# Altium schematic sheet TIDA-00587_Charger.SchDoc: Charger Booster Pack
size 431 x 279 mm; VersionControl_RevNumber: E3; Date: Not shown in title block; ApprovedBy: Not shown in title block; CheckedBy: Gordon Varney; Author: Gordon Varney; CompanyName: Texas Instruments; DrawnBy: Gordon Varney; Engineer: Gordon Varney; Organization: Not shown in title block; Address1: Not shown in title block; Address2: Not shown in title block; Address3: Not shown in title block; Address4: Not shown in title block; DocumentNumber: 1; Revision: Use project parameter SCH_Rev; SheetNumber: 1; SheetTotal: 2; PageSetup: Record=PageOptions¦CenterHorizontal=True¦CenterVertical=True¦PrintScale=0.64¦XCorrection=1.00¦YCorrection=1.00¦PrintKind=0¦BorderSize=5000000¦LeftOffset=0¦BottomOffset=0¦Orientation=2¦PaperLength=1000¦PaperWidth=1000¦Scale=100¦PaperSource=15¦PrintQuality=600¦MediaType=1¦DitherType=10¦PrintScaleMode=1¦PaperKind=Letter
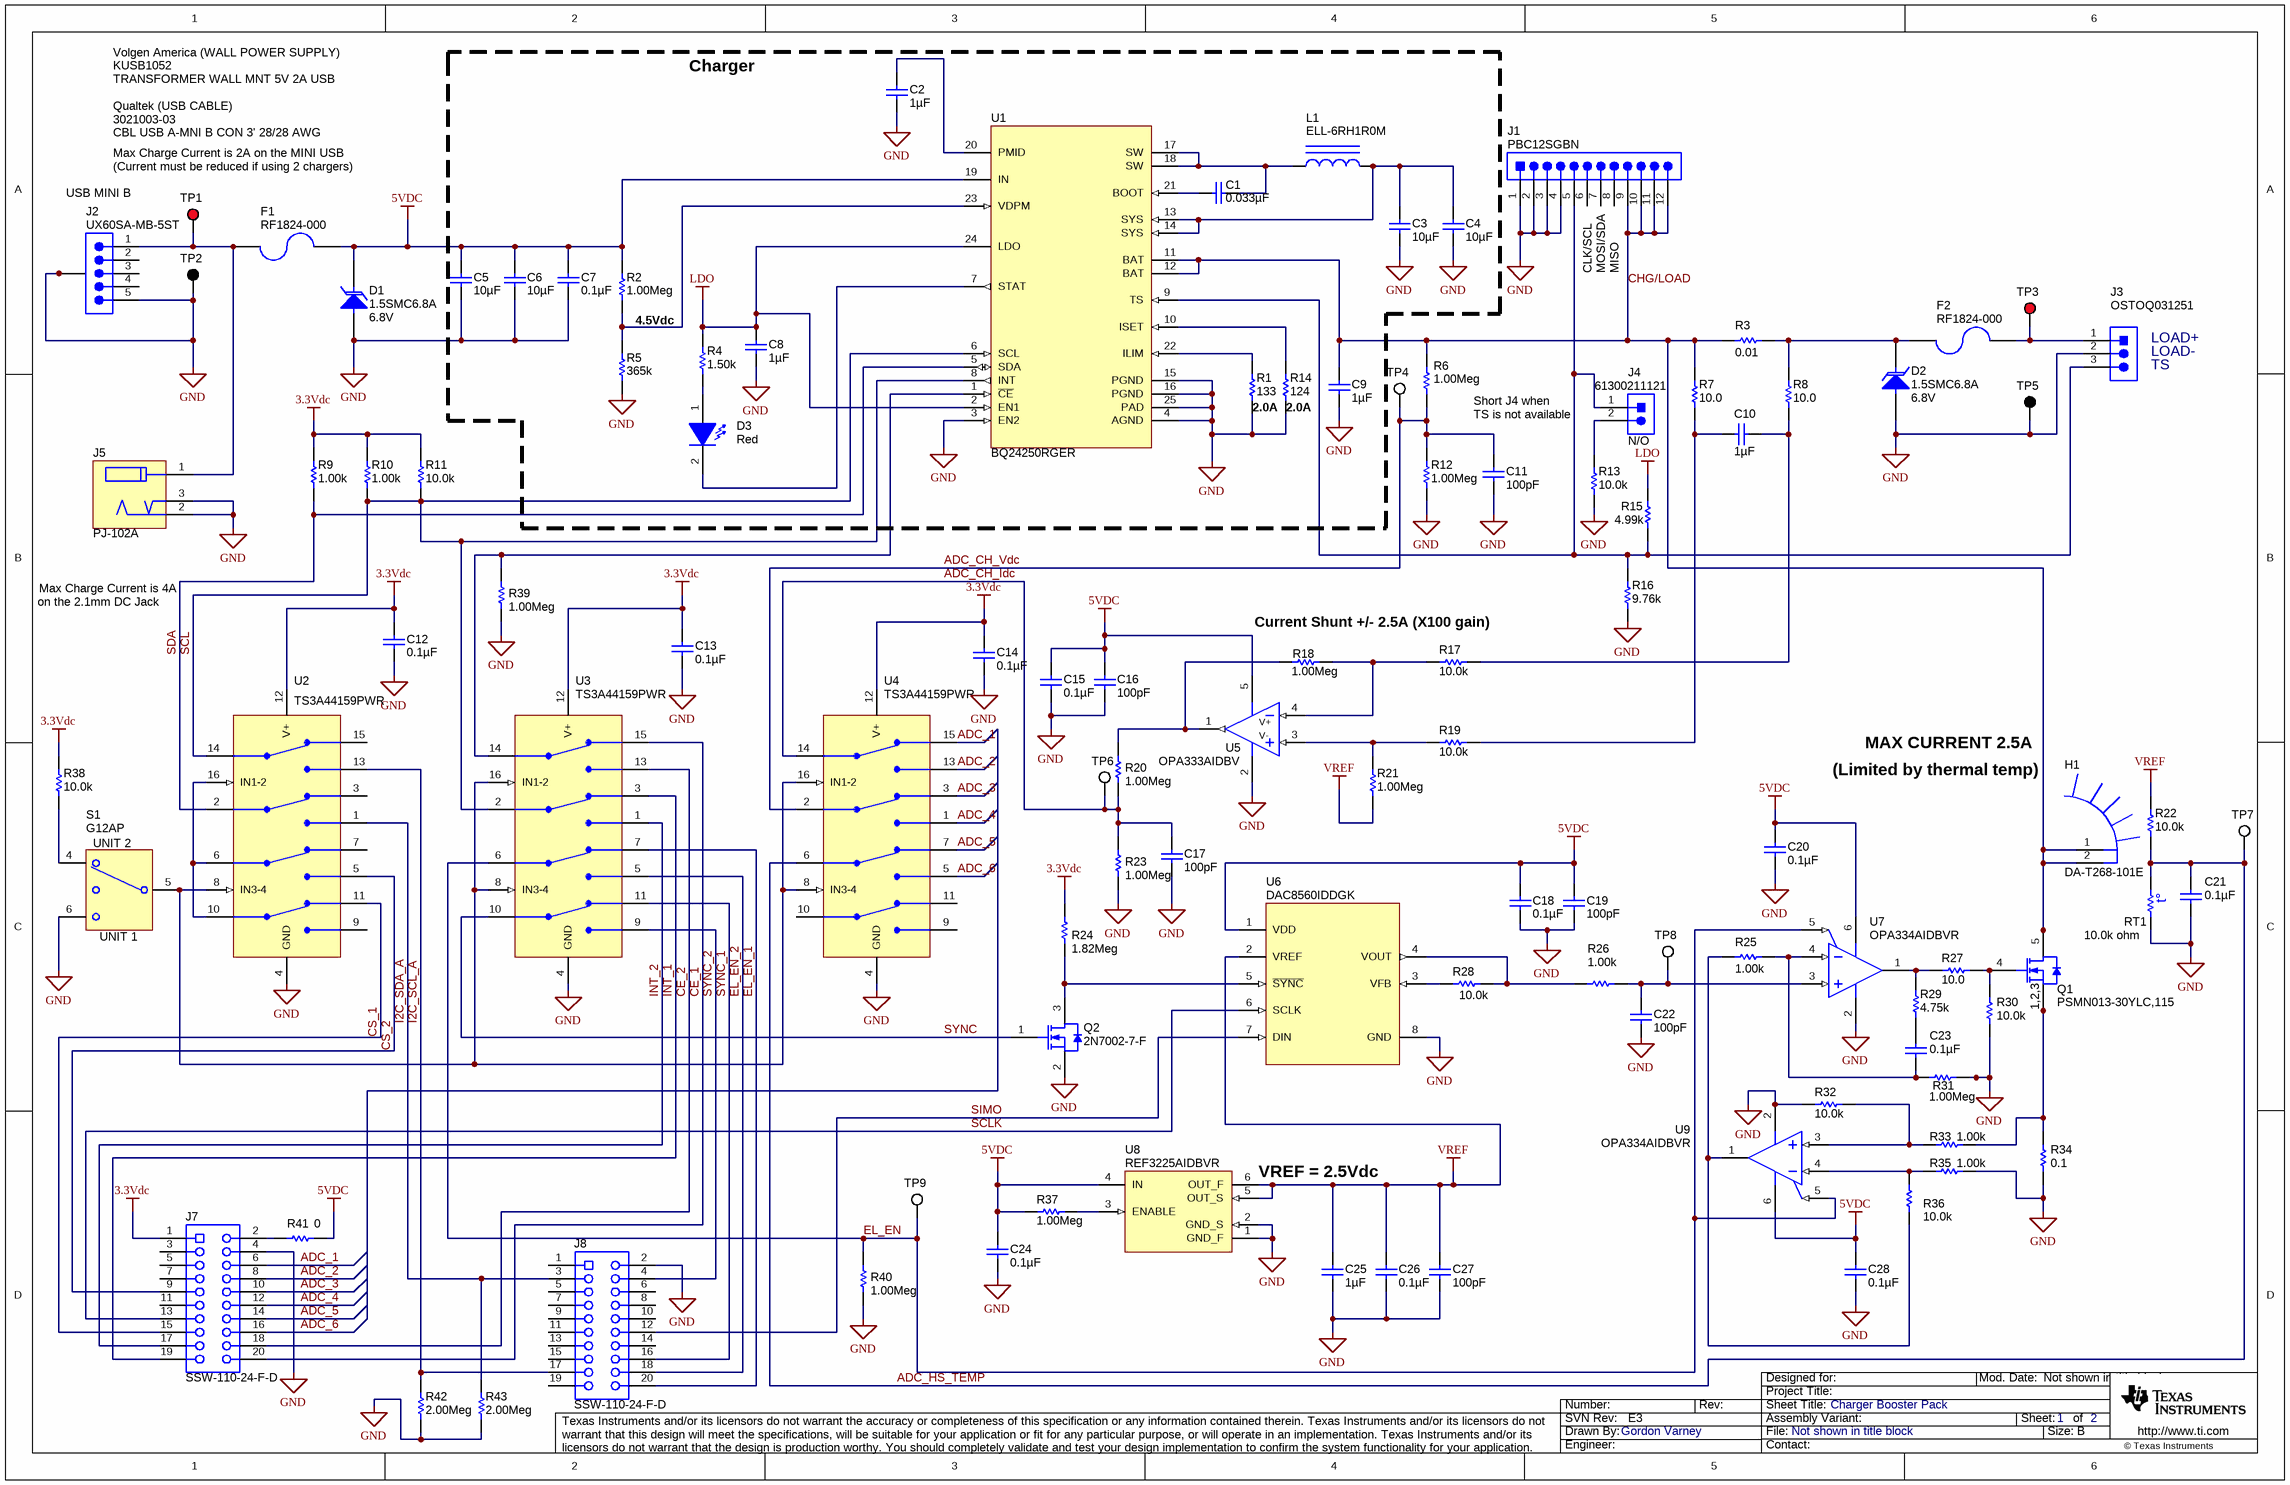
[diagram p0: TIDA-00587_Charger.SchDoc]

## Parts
C1  ValueDisplayed: 0.033µF  [0603]  (hidden comment: GRM188R71H333KA61D)
C2  ValueDisplayed: 1µF  [0805_HV]  (hidden comment: GRM21BR71E105KA99L)
C3  ValueDisplayed: 10µF  [0805_HV]  (hidden comment: GRM21BR61A106KE19L)
C4  ValueDisplayed: 10µF  [0805_HV]  (hidden comment: GRM21BR61A106KE19L)
C5  ValueDisplayed: 10µF  [0805_HV]  (hidden comment: GRM21BR61A106KE19L)
C6  ValueDisplayed: 10µF  [0805_HV]  (hidden comment: GRM21BR61A106KE19L)
C7  ValueDisplayed: 0.1µF  [0603]  (hidden comment: C0603C104K3RACTU)
C8  ValueDisplayed: 1µF  [0805_HV]  (hidden comment: GRM21BR71E105KA99L)
C9  ValueDisplayed: 1µF  [0805_HV]  (hidden comment: GRM21BR71E105KA99L)
C10  ValueDisplayed: 1µF  [0805_HV]  (hidden comment: GRM21BR71E105KA99L)
C11  ValueDisplayed: 100pF  [0603]  (hidden comment: C0603C101J5GACTU)
C12  ValueDisplayed: 0.1µF  [0603]  (hidden comment: C0603C104K3RACTU)
C13  ValueDisplayed: 0.1µF  [0603]  (hidden comment: C0603C104K3RACTU)
C14  ValueDisplayed: 0.1µF  [0603]  (hidden comment: C0603C104K3RACTU)
C15  ValueDisplayed: 0.1µF  [0603]  (hidden comment: C0603C104K3RACTU)
C16  ValueDisplayed: 100pF  [0603]  (hidden comment: GRM1885C1H101JA01D)
C17  ValueDisplayed: 100pF  [0603]  (hidden comment: C0603C101J5GACTU)
C18  ValueDisplayed: 0.1µF  [0603]  (hidden comment: C0603C104K3RACTU)
C19  ValueDisplayed: 100pF  [0603]  (hidden comment: GRM1885C1H101JA01D)
C20  ValueDisplayed: 0.1µF  [0603]  (hidden comment: C0603C104K3RACTU)
C21  ValueDisplayed: 0.1µF  [0603]  (hidden comment: GRM188R71E104KA01D)
C22  ValueDisplayed: 100pF  [0603]  (hidden comment: C0603C101J5GACTU)
C23  ValueDisplayed: 0.1µF  [0603]  (hidden comment: GRM188R71E104KA01D)
C24  ValueDisplayed: 0.1µF  [0603]  (hidden comment: C0603C104K3RACTU)
C25  ValueDisplayed: 1µF  [0805_HV]  (hidden comment: GRM21BR71E105KA99L)
C26  ValueDisplayed: 0.1µF  [0603]  (hidden comment: C0603C104K3RACTU)
C27  ValueDisplayed: 100pF  [0603]  (hidden comment: GRM1885C1H101JA01D)
C28  ValueDisplayed: 0.1µF  [0603]  (hidden comment: C0603C104K3RACTU)
D1  1.5SMC6.8A  value 6.8V  [SMC]
D2  1.5SMC6.8A  value 6.8V  [SMC]
D3  value Red  [LED_LTST-C190_Red]  (hidden comment: LTST-C190CKT)
F1  RF1824-000  [FUSE_LR2]
F2  RF1824-000  [FUSE_LR2]
H1  DA-T268-101E  [Ohmite_DA-T268-101E]
J1  PBC12SGBN  [Sullins_PBC12SGBN]
J2  UX60SA-MB-5ST  [UX60SA-MB-5ST]
J3  OSTOQ031251  [On-Shore_OSTOQ031251]
J4  61300211121  [WURTH_61300211121]
J5  PJ-102A  [CONN_PJ-102A]
J7  SSW-110-24-F-D  [CONN_SSW-110-23-F-D]
J8  SSW-110-24-F-D  [CONN_SSW-110-23-F-D]
L1  ELL-6RH1R0M  [ELL6RH]
Q1  PSMN013-30YLC,115  [LFPAK]
Q2  2N7002-7-F  [SOT-23]
R1  value 133  [0603]  (hidden comment: CRCW0603133RFKEA)
R2  value 1.00Meg  [0603]  (hidden comment: CRCW06031M00FKEA)
R3  value 0.01  [1206]  (hidden comment: LVK12R010DER)
R4  value 1.50k  [0603]  (hidden comment: CRCW06031K50FKEA)
R5  value 365k  [0603]  (hidden comment: CRCW0603365KFKEA)
R6  value 1.00Meg  [0603]  (hidden comment: CRCW06031M00FKEA)
R7  value 10.0  [0603]  (hidden comment: CRCW060310R0FKEA)
R8  value 10.0  [0603]  (hidden comment: CRCW060310R0FKEA)
R9  value 1.00k  [0603]  (hidden comment: CRCW06031K00FKEA)
R10  value 1.00k  [0603]  (hidden comment: CRCW06031K00FKEA)
R11  value 10.0k  [0603]  (hidden comment: CRCW060310K0FKEA)
R12  value 1.00Meg  [0603]  (hidden comment: CRCW06031M00FKEA)
R13  value 10.0k  [0603]  (hidden comment: CRCW060310K0FKEA)
R14  value 124  [0603]  (hidden comment: CRCW0603124RFKEA)
R15  value 4.99k  [0603]  (hidden comment: CRCW06034K99FKEA)
R16  value 9.76k  [0603]  (hidden comment: CRCW06039K76FKEA)
R17  value 10.0k  [0603]  (hidden comment: CRCW060310K0FKEA)
R18  value 1.00Meg  [0603]  (hidden comment: CRCW06031M00FKEA)
R19  value 10.0k  [0603]  (hidden comment: CRCW060310K0FKEA)
R20  value 1.00Meg  [0603]  (hidden comment: CRCW06031M00FKEA)
R21  value 1.00Meg  [0603]  (hidden comment: CRCW06031M00FKEA)
R22  value 10.0k  [0603]  (hidden comment: CRCW060310K0FKEA)
R23  value 1.00Meg  [0603]  (hidden comment: CRCW06031M00FKEA)
R24  value 1.82Meg  [0603]  (hidden comment: CRCW06031M82FKEA)
R25  value 1.00k  [0603]  (hidden comment: CRCW06031K00FKEA)
R26  value 1.00k  [0603]  (hidden comment: CRCW06031K00FKEA)
R27  value 10.0  [0603]  (hidden comment: CRCW060310R0FKEA)
R28  value 10.0k  [0603]  (hidden comment: CRCW060310K0FKEA)
R29  value 4.75k  [0603]  (hidden comment: CRCW06034K75FKEA)
R30  value 10.0k  [0603]  (hidden comment: CRCW060310K0FKEA)
R31  value 1.00Meg  [0603]  (hidden comment: CRCW06031M00FKEA)
R32  value 10.0k  [0603]  (hidden comment: CRCW060310K0FKEA)
R33  value 1.00k  [0603]  (hidden comment: CRCW06031K00FKEA)
R34  value 0.1  [2010M]  (hidden comment: CSRN2010FKR100)
R35  value 1.00k  [0603]  (hidden comment: CRCW06031K00FKEA)
R36  value 10.0k  [0603]  (hidden comment: CRCW060310K0FKEA)
R37  value 1.00Meg  [0603]  (hidden comment: CRCW06031M00FKEA)
R38  value 10.0k  [0603]  (hidden comment: CRCW060310K0FKEA)
R39  value 1.00Meg  [0603]  (hidden comment: CRCW06031M00FKEA)
R40  value 1.00Meg  [0603]  (hidden comment: CRCW06031M00FKEA)
R41  ValueDisplayed: 0  [0603]  (hidden comment: CRCW06030000Z0EA)
R42  value 2.00Meg  [0603]  (hidden comment: CRCW06032M00FKEA)
R43  value 2.00Meg  [0603]  (hidden comment: CRCW06032M00FKEA)
RT1  value 10.0k ohm  [0603]  (hidden comment: ERT-J1VG103FA)
S1  G12AP  [SW_G1xAP]
TP1  5000  [Keystone5000]  (value not drawn)
TP2  5001  [Keystone5001]  (value not drawn)
TP3  5000  [Keystone5000]  (value not drawn)
TP4  5002  [Keystone5002]  (value not drawn)
TP5  5001  [Keystone5001]  (value not drawn)
TP6  5002  [Keystone5002]  (value not drawn)
TP7  5002  [Keystone5002]  (value not drawn)
TP8  5002  [Keystone5002]  (value not drawn)
TP9  5002  [Keystone5002]  (value not drawn)
U1  BQ24250RGER  [RGE0024H_NV]
U2  TS3A44159PWR  [PW0016A_N]
U3  TS3A44159PWR  [PW0016A_N]
U4  TS3A44159PWR  [PW0016A_N]
U5  OPA333AIDBV  [DBV0005A_N]
U6  DAC8560IDDGK  [DGK0008A_N]
U7  OPA334AIDBVR  [DBV0006A_N]
U8  REF3225AIDBVR  [DBV0006A_N]
U9  OPA334AIDBVR  [DBV0006A_N]

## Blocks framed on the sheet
Charger: C1-C9 D3 L1 R1 R2 R4 R5 R14 U1

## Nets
3.3Vdc: C12.1 C13.1 C14.1 J7.1 R9.2 R10.2 R11.2 R24.1 R38.2 U2.12(V+) U3.12(V+) U4.12(V+)
5VDC: C5.1 C6.1 C7.1 C15.1 C16.1 C18.1 C19.1 C20.1 C24.1 C28.1 D1.1(K) F1.2 R2.2 R37.2 R41.1 U1.19(IN) U5.5(V+) U6.1(VDD) U7.6(V+) U8.4(IN) U9.6(V+)
GND: C2.1 C3.2 C4.2 C5.2 C6.2 C7.2 C8.1 C9.1 C11.2 C12.2 C13.2 C14.2 C15.2 C16.2 C17.2 C18.2 C19.2 C20.2 C21.2 C22.2 C24.2 C25.1 C26.2 C27.2 C28.2 D1.2(A) D2.2(A) J1.1 J1.2 J1.3 J1.4 J2.5 J2.6(GND) J2.7(GND) J2.8(GND) J2.9(GND) J3.2 J5.2 J5.3 J7.4 J8.2 Q2.2(S) R1.1 R5.1 R12.1 R13.1 R14.1 R16.1 R23.1 R30.1 R31.2 R32.2 R34.1 R35.2 R39.1 R40.1 R42.1 R43.1 RT1.1 S1.6 TP2.1 TP5.1 U1.3(EN2) U1.4(AGND) U1.15(PGND) U1.16(PGND) U1.25(PAD) U2.4(GND) U3.4(GND) U4.4(GND) U5.2(V-) U6.8(GND) U7.2(V-) U8.1(GND_F) U8.2(GND_S) U9.2(V-)
LDO: C8.2 R4.1 R15.2 U1.2(EN1) U1.24(LDO)
VREF: C25.2 C26.1 C27.1 R21.2 R22.2 U6.2(VREF) U8.5(OUT_S) U8.6(OUT_F)
ADC_1: J7.6 U4.15(NC1)
ADC_2: J7.8 U4.13(NO1)
ADC_3: J7.10 U4.3(NC2)
ADC_4: J7.12 U4.1(NO2)
ADC_5: J7.14 U4.7(NC3)
ADC_6: J7.16 U4.5(NO3)
ADC_CH_Idc: C17.1 R20.1 R23.2 TP6.1 U4.14(COM1)
ADC_CH_Vdc: C11.1 R6.1 R12.2 TP4.1 U4.2(COM2)
ADC_HS_TEMP: C21.1 R22.1 RT1.2 TP7.1 U4.6(COM3)
CE_1: J7.20 U3.15(NC1)
CE_2: J7.18 U3.13(NO1)
CHG/LOAD: C9.2 H1.1 H1.2 J1.9 J1.10 J1.11 J1.12 Q1.5(D) Q1.6(D) R3.1 R6.2 R7.2 U1.11(BAT) U1.12(BAT)
CS_1: J7.15 U2.11(NC4)
CS_2: J7.9 U2.5(NO3)
EL_EN: R40.2 TP9.1 U3.6(COM3) U7.5(ENABLE) U9.5(ENABLE)
EL_EN_1: J8.20 U3.7(NC3)
EL_EN_2: J8.18 U3.5(NO3)
I2C_SCL_A: J8.17 R42.2 U2.13(NO1)
I2C_SDA_A: J8.3 R43.2 U2.1(NO2)
INT_1: J7.19 U3.3(NC2)
INT_2: J7.17 U3.1(NO2)
SCL: R10.1 R11.1 U1.6(SCL) U1.8(INT) U2.14(COM1) U3.2(COM2)
SCLK: J7.13 U6.6(SCLK)
SDA: R9.1 U1.5(SDA) U2.2(COM2)
SIMO: J8.12 U6.7(DIN)
SYNC: Q2.1(G) U3.10(COM4)
SYNC_1: J8.16 U3.11(NC4)
SYNC_2: J8.4 U3.9(NO4)
NetC1_1: C1.1 L1.1 U1.17(SW) U1.18(SW)
NetC1_2: C1.2 U1.21(BOOT)
NetC2_2: C2.2 U1.20(PMID)
NetC3_1: C3.1 C4.1 L1.2 U1.13(SYS) U1.14(SYS)
NetC10_1: C10.1 R8.1 R17.2
NetC10_2: C10.2 R7.1 R19.2
NetC22_1: C22.1 R26.2 TP8.1 U7.3(IN+)
NetC23_1: C23.1 R29.1
NetC23_2: C23.2 R25.2 R31.1 U7.4(IN-)
NetD2_1: D2.1(K) F2.1 R3.2 R8.2
NetD3_1: D3.1(A) R4.2
NetD3_2: D3.2(K) U1.7(STAT)
NetF1_1: F1.1 J2.1 J5.1 TP1.1
NetF2_2: F2.2 J3.1 TP3.1
NetJ1_5: J1.5 J3.3 J4.1 R15.1 R16.2 U1.9(TS)
NetJ4_2: J4.2 R13.2
NetJ7_2: J7.2 R41.2
NetQ1_1: Q1.1(S) Q1.2(S) Q1.3(S) R33.2 R34.2
NetQ1_4: Q1.4(G) R27.2 R30.2
NetQ2_3: Q2.3(D) R24.2 U6.5(~{SYNC})
NetR1_2: R1.2 U1.22(ILIM)
NetR2_1: R2.1 R5.2 U1.23(VDPM)
NetR14_2: R14.2 U1.10(ISET)
NetR17_1: R17.1 R18.1 U5.4(IN-)
NetR18_2: R18.2 R20.2 U5.1(OUT)
NetR19_1: R19.1 R21.1 U5.3(IN+)
NetR25_1: R25.1 R36.1 U9.1(OUT)
NetR26_1: R26.1 R28.2 U6.4(VOUT)
NetR27_1: R27.1 R29.2 U7.1(OUT)
NetR28_1: R28.1 U6.3(VFB)
NetR32_1: R32.1 R33.1 U9.3(IN+)
NetR35_1: R35.1 R36.2 U9.4(IN-)
NetR37_1: R37.1 U8.3(ENABLE)
NetR38_1: R38.1 S1.4
NetR39_2: R39.2 U1.1(~{CE}) U3.14(COM1)
NetS1_5: S1.5(COM) U2.8(IN3-4) U3.8(IN3-4) U3.16(IN1-2) U4.8(IN3-4) U4.16(IN1-2)
NetU2_6: U2.6(COM3) U2.10(COM4) U2.16(IN1-2)

Not connected (* = marked no-connect by the designer): J1 6 7 8; J2 2 3 4; J7 3 5 7 11; J8 1 5 6 7 8 9 10 11 13 14 15 19; U2 3(NC2) 7(NC3) 9(NO4) 15(NC1); U4 9(NO4) 10(COM4) 11(NC4)

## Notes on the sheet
- Volgen America (WALL POWER SUPPLY)
- KUSB1052
- TRANSFORMER WALL MNT 5V 2A USB
- Qualtek (USB CABLE)
- 3021003-03
- CBL USB A-MNI B CON 3' 28/28 AWG
- Max Charge Current is 2A on the MINI USB
- (Current must be reduced if using 2 chargers)
- USB MINI B
- (near J1) CLK/SCL
- (near J1) MOSI/SDA
- MISO
- 4.5Vdc
- (near J3) LOAD+
- (near J3) LOAD-
- (near R1) 2.0A
- (near R14) 2.0A
- Short J4 when
- TS is not available
- (near J4) N/O
- (near J3) TS
- Max Charge Current is 4A
- on the 2.1mm DC Jack
- Current Shunt +/- 2.5A (X100 gain)
- (Limited by thermal temp)
- MAX CURRENT 2.5A
- (near S1) UNIT 2
- (near S1) UNIT 1
- (near U8) VREF = 2.5Vdc

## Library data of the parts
C1 = GRM188R71H333KA61D: CAP, CERM, 0.033uF, 50V, +/-10%, X7R, 0603; Manufacturer: MuRata; Polarized: N; CompType: Capacitor; U/M: EA; Cap_F: 0.000000033; Tolerance_%: 10; Value1: Unknown; VDC_V: 50; TaMin_C: -55; TaMax_C: 125
C2 C8-C10 C25 = GRM21BR71E105KA99L: CAP, CERM, 1uF, 25V, +/-10%, X7R, 0805; Manufacturer: MuRata; Polarized: N; CompType: Capacitor; U/M: EA; Cap_F: 0.000001; Tolerance_%: 10; Value1: Unknown; VDC_V: 25; TaMin_C: -55; TaMax_C: 125; Cap_Case: 0805
C3-C6 = GRM21BR61A106KE19L: CAP, CERM, 10uF, 10V, +/-10%, X5R, 0805; Manufacturer: MuRata; Polarized: N; CompType: Capacitor; U/M: EA; Cap_F: 0.00001; Tolerance_%: 10; ESR_Ohm: 0.002; Value1: 0.002 ohm; TaMin_C: -55; TaMax_C: 85; Cap_Case: 0805
C7 C12-C15 C18 C20 C24 C26 C28 = C0603C104K3RACTU: CAP, CERM, 0.1uF, 25V, +/-10%, X7R, 0603; Manufacturer: Kemet; Polarized: N; CompType: Capacitor; U/M: EA; Cap_F: 0.0000001; Tolerance_%: 10; Value1: Unknown; VDC_V: 25; TaMin_C: -55; TaMax_C: 125
C11 C17 C22 = C0603C101J5GACTU: CAP, CERM, 100pF, 50V, +/-5%, C0G/NP0, 0603; Manufacturer: Kemet; Polarized: N; CompType: Capacitor; U/M: EA; Cap_F: 0.0000000001; Tolerance_%: 5; Value1: Unknown; VDC_V: 50; TaMin_C: -55; TaMax_C: 125
C16 C19 C27 = GRM1885C1H101JA01D: CAP, CERM, 100pF, 50V, +/-5%, C0G/NP0, 0603; Manufacturer: MuRata; Polarized: N; CompType: Capacitor; U/M: EA; Cap_F: 0.0000000001; Tolerance_%: 5; Value1: Unknown; VDC_V: 50; TaMin_C: -55; TaMax_C: 125
C21 C23 = GRM188R71E104KA01D: CAP, CERM, 0.1uF, 25V, +/-10%, X7R, 0603; Manufacturer: MuRata; Polarized: N; CompType: Capacitor; U/M: EA; Cap_F: 0.0000001; Tolerance_%: 10; Value1: Unknown; VDC_V: 25; TaMin_C: -55; TaMax_C: 125
D1 D2 = 1.5SMC6.8A: Diode, TVS, Uni, 6.8V, 1500W, SMC; Manufacturer: Littelfuse; U/M: EA; Power_W: 1500; Vr_V: 6.8; RJA_CperW: 75
D3 = LTST-C190CKT: LED, Red, SMD; Manufacturer: Lite-On; Vf_V: 2; Value2: 2V; Io_A: 0.02; Tjmax_C: 85; Power_TotalModule: 0.0625; Value1: 0.0625W; U/M: EA
F1 F2 = RF1824-000: Fuse, Resettable, 1.9A, 6V, SMD; Manufacturer: TE Connectivity; SymbolCreator: a0412235; U/M: EA; VDC_V: 6; Irating_A: 1.9; Rtyp_Ohm: 0.021; MeltingTyp: 3
H1 = DA-T268-101E: Heatsink, TO-268 [D3]SMT; Manufacturer: Ohmite; SymbolCreator: a0799628
J1 = PBC12SGBN: Header, 12x1, 100mil, R/A, TH; Manufacturer: Sullins Connector Solutions; SymbolCreator: a0412235; U/M: EA
J2 = UX60SA-MB-5ST: Connector, Receptacle, Mini-USB Type B, R/A, Top Mount SMT; Manufacturer: Hirose Electric Co. Ltd.; SymbolCreator: a0412235; U/M: EA
J3 = OSTOQ031251: Header, 3x1 3.5mm, TH; Manufacturer: On-Shore Technology; SymbolCreator: a0799628; Note: Mating Part number: OSTTJ0311530; U/M: EA
J4 = 61300211121: Header, 2.54 mm, 2x1, Gold, TH; Manufacturer: Wurth Elektronik; SymbolCreator: a0412235; U/M: EA
J5 = PJ-102A: Connector, DC Jack 2.1X5.5 mm, TH; Manufacturer: CUI Inc.; SymbolCreator: a0799628; U/M: EA
J7 J8 = SSW-110-23-F-D: Connector, Receptacle, 100mil, 10x2, Gold plated, TH; Manufacturer: Samtec; SymbolCreator: a0412235; U/M: EA
L1 = ELL-6RH1R0M: Inductor, Shielded Drum Core, Ferrite, 1uH, 3A, 0.019 ohm, SMD; Manufacturer: Panasonic; Ind_H: 1.0E-6; ValueDisplayed: 1µH; Imax_A: 3; Irms: 3A @ 45C rise; Isat: 3A @ 20% inductance drop; DCR_ohm: 0.019; U/M: EA
Q1 = PSMN013-30YLC,115: MOSFET, N-CH, 30V, 32A, LFPAK; Manufacturer: NXP Semiconductor; Alternate Manufacturer: None; U/M: EA; ChType: N; VdsMax_V: 30; Value1: 0.0169 ohm; Rdson45_Ohm: 0.0169; Value2: 8.3 nC; QgTyp_nC: 8.3; Vgs_V: 20; IdsMax_A: 32
Q2 = 2N7002-7-F: MOSFET, N-CH, 60V, 0.17A, SOT-23; Manufacturer: Diodes Inc.; Alternate Manufacturer: None; U/M: EA; ChType: N; VdsMax_V: 60; Value1: 7.5 ohm; Rdson45_Ohm: 7.5; Value2: 223 nC; QgTyp_nC: 223; Vgs_V: 20; IdsMax_A: 0.17
R1 = CRCW0603133RFKEA: RES, 133 ohm, 1%, 0.1W, 0603; Manufacturer: Vishay-Dale; CompType: Resistor; Value_Code: 133R; Tolerance_%: 1; Power_W: 0.1; VDC_V: 75; TempCo: 100 ppm/C; EIA_Code: E96; U/M: EA
R2 R6 R12 R18 R20 R21 R23 R31 R37 R39 R40 = CRCW06031M00FKEA: RES, 1.00Meg ohm, 1%, 0.1W, 0603; Manufacturer: Vishay-Dale; CompType: Resistor; Res_ohm: 1000000; Value_Code: 1M00; Tolerance_%: 1; Power_W: 0.1; VDC_V: 75; TempCo: 100 ppm/C; EIA_Code: E96; U/M: EA
R3 = LVK12R010DER: RES, 0.01 ohm, 0.5%, 0.5W, 1206; Manufacturer: Ohmite; CompType: Resistor; Value_Code: R010; Tolerance_%: 0.5; TempCo: 50 ppm/C; U/M: EA
R4 = CRCW06031K50FKEA: RES, 1.50k ohm, 1%, 0.1W, 0603; Manufacturer: Vishay-Dale; CompType: Resistor; Res_ohm: 1500; Value_Code: 1k50; Tolerance_%: 1; Power_W: 0.1; VDC_V: 75; TempCo: 100 ppm/C; EIA_Code: E96; U/M: EA
R5 = CRCW0603365KFKEA: RES, 365k ohm, 1%, 0.1W, 0603; Manufacturer: Vishay-Dale; CompType: Resistor; Res_ohm: 365000; Tolerance_%: 1; Power_W: 0.1; VDC_V: 75; TempCo: 100 ppm/C; EIA_Code: E96; U/M: EA
R7 R8 R27 = CRCW060310R0FKEA: RES, 10.0 ohm, 1%, 0.1W, 0603; Manufacturer: Vishay-Dale; CompType: Resistor; Res_ohm: 10; Value_Code: 10R0; Tolerance_%: 1; Power_W: 0.1; VDC_V: 75; TempCo: 100 ppm/C; EIA_Code: E96; U/M: EA
R9 R10 R25 R26 R33 R35 = CRCW06031K00FKEA: RES, 1.00k ohm, 1%, 0.1W, 0603; Manufacturer: Vishay-Dale; CompType: Resistor; Res_ohm: 1000; Value_Code: 1k00; Tolerance_%: 1; Power_W: 0.1; VDC_V: 75; TempCo: 100 ppm/C; EIA_Code: E96; U/M: EA
R11 R13 R17 R19 R22 R28 R30 R32 R36 R38 = CRCW060310K0FKEA: RES, 10.0k ohm, 1%, 0.1W, 0603; Manufacturer: Vishay-Dale; CompType: Resistor; Res_ohm: 10000; Value_Code: 10k0; Tolerance_%: 1; Power_W: 0.1; VDC_V: 75; TempCo: 100 ppm/C; EIA_Code: E96; U/M: EA
R14 = CRCW0603124RFKEA: RES, 124 ohm, 1%, 0.1W, 0603; Manufacturer: Vishay-Dale; CompType: Resistor; Value_Code: 124R; Tolerance_%: 1; Power_W: 0.1; VDC_V: 75; TempCo: 100 ppm/C; EIA_Code: E96; U/M: EA
R15 = CRCW06034K99FKEA: RES, 4.99k ohm, 1%, 0.1W, 0603; Manufacturer: Vishay-Dale; CompType: Resistor; Res_ohm: 4990; Value_Code: 4k99; Tolerance_%: 1; Power_W: 0.1; VDC_V: 75; TempCo: 100 ppm/C; EIA_Code: E96; U/M: EA
R16 = CRCW06039K76FKEA: RES, 9.76k ohm, 1%, 0.1W, 0603; Manufacturer: Vishay-Dale; CompType: Resistor; Res_ohm: 9760; Value_Code: 9k76; Tolerance_%: 1; Power_W: 0.1; VDC_V: 75; TempCo: 100 ppm/C; EIA_Code: E96; U/M: EA
R24 = CRCW06031M82FKEA: RES, 1.82Meg ohm, 1%, 0.1W, 0603; Manufacturer: Vishay-Dale; CompType: Resistor; Res_ohm: 1820000; Value_Code: 1M82; Tolerance_%: 1; Power_W: 0.1; VDC_V: 75; TempCo: 100 ppm/C; EIA_Code: E96; U/M: EA
R29 = CRCW06034K75FKEA: RES, 4.75k ohm, 1%, 0.1W, 0603; Manufacturer: Vishay-Dale; CompType: Resistor; Res_ohm: 4750; Value_Code: 4k75; Tolerance_%: 1; Power_W: 0.1; VDC_V: 75; TempCo: 100 ppm/C; EIA_Code: E96; U/M: EA
R34 = CSRN2010FKR100: RES, 0.1 ohm, 1%, 1W, 2010; Manufacturer: Stackpole Electronics Inc; CompType: Resistor; Value_Code: R100; Tolerance_%: 1; TempCo: 250 ppm/C; EIA_Code: E96; U/M: EA
R41 = CRCW06030000Z0EA: RES, 0, 5%, 0.1 W, 0603; Manufacturer: Vishay-Dale; CompType: Resistor; Value: 0; Value_Code: 0000; Tolerance_%: 5; Power_W: 0.1; Value2: 0.1W; VDC_V: 75; TempCo: 200 ppm/C; EIA_Code: E24; U/M: EA
R42 R43 = CRCW06032M00FKEA: RES, 2.00Meg ohm, 1%, 0.1W, 0603; Manufacturer: Vishay-Dale; CompType: Resistor; Res_ohm: 2000000; Value_Code: 2M00; Tolerance_%: 1; Power_W: 0.1; VDC_V: 75; TempCo: 100 ppm/C; EIA_Code: E96; U/M: EA
RT1 = ERT-J1VG103FA: Thermistor NTC, 10.0k ohm, 1%, 0603; Manufacturer: Panasonic; Tolerance_%: 1; Power_W: 0.1; TaMin_C: -40; TaMax_C: 125; U/M: EA
S1 = G12AP: Switch, Toggle, SPDT 1Pos, TH; Manufacturer: NKK Switches; SymbolCreator: a0412235; VDC_V: 28; SwitchFunction: On-On; PositionCount: 1; CurrentRating_mA: 400
TP1 TP3 = 5000: Test Point, Miniature, Red, TH; Manufacturer: Keystone; CompType: Test Point Loop; U/M: EA
TP2 TP5 = 5001: Test Point, Miniature, Black, TH; Manufacturer: Keystone; CompType: Test Point Loop; U/M: EA
TP4 TP6-TP9 = 5002: Test Point, Miniature, White, TH; Manufacturer: Keystone; CompType: Test Point Loop; U/M: EA
U1 = BQ24250RGER: 2A Single Input I2C, Standalone Switch-Mode Li-Ion Battery Charger with Power-Path Management, RGE0024H; Alternate PartNumber: BQ24250RGET; Manufacturer: Texas Instruments; SymbolCreator: a0411947; CompType: IC; U/M: EA
U2-U4 = TS3A44159PWR: 0.45 ohm QUAD SPDT ANALOG SWITCH QUAD-CHANNEL 2:1 MULTIPLEXER/DEMULTIPLEXER WITH TWO CONTROLS, PW0016A; Alternate Manufacturer: None; Manufacturer: Texas Instruments; SymbolCreator: a0411947; CompType: IC; U/M: EA
U5 = OPA333AIDBV: 1.8-V, microPower, CMOS Operational Amplifiers, Zero-Drift Series, DBV0005A; Alternate Manufacturer: None; Manufacturer: Texas Instruments; CompType: IC; U/M: EA
U6 = DAC8560IDDGK: 16-Bit, Ultra-Low Glitch, Voltage Output Digital-to-Analog Converter with 2.5V, 2ppm/°C Internal Reference, DGK0008A; Manufacturer: Texas Instruments; SymbolCreator: a0411947; CompType: IC; U/M: EA
U7 U9 = OPA334AIDBVR: 0.05 uV/C Max, Single-Supply CMOS Operational Amplifier, 2.7 to 5.5 V, -40 to 125 degC, 6-pin SOT23 (DBV0006A), Green (RoHS & no Sb/Br); Manufacturer: Texas Instruments; Alternate Manufacturer: None; Alternate PartNumber: Equivalent; CMRR(Min)(dB): 110; IIB(Max)(pA): 200; Iq per channel(Max)(mA): 0.35; Number of Channels: 1; Offset Drift(Typ)(uV/C): 0.02; Slew Rate(Typ)(V/us): 1.6; Sub Family: Low Offset Voltage Amplifier (<=500uV), Low Power Amp (<=500uA), Low Supply Voltage Amplifier (<=2.7V), Precision Amplifier, Zero Drift Precision Amplifier; Total Supply Voltage(Max)(+5V is 5, +/-5V is 10): 5.5; Total Supply Voltage(Min)(+5V is 5, +/-5V is 10): 2.7; Vio (25C)(Max)(mV): 0.005
U8 = REF3225AIDBVR: 2.5 V, 4 ppm / degC, 100 uA Series (Bandgap) Voltage Reference, -40 to 125 degC, 6-pin SOT-23 (DBV), Green (RoHS & no Sb/Br); Manufacturer: Texas Instruments; Alternate Manufacturer: None; Alternate PartNumber: Equivalent; Initial Accuracy @ 25/deg C(%): 0.2; Iout/Iz(Max)(mA): 10; Iq(Max)(uA): 120; Rating: Catalog; SubFamily: Series Voltage Reference; Temp Coeff(Max)(ppm/ degree C): 7; Temp Coeff(Typ)(ppm/ degree C): 4; VI(Max)(V): 5.5; VI(Min)(V): 2.55; VO(V): 2.5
